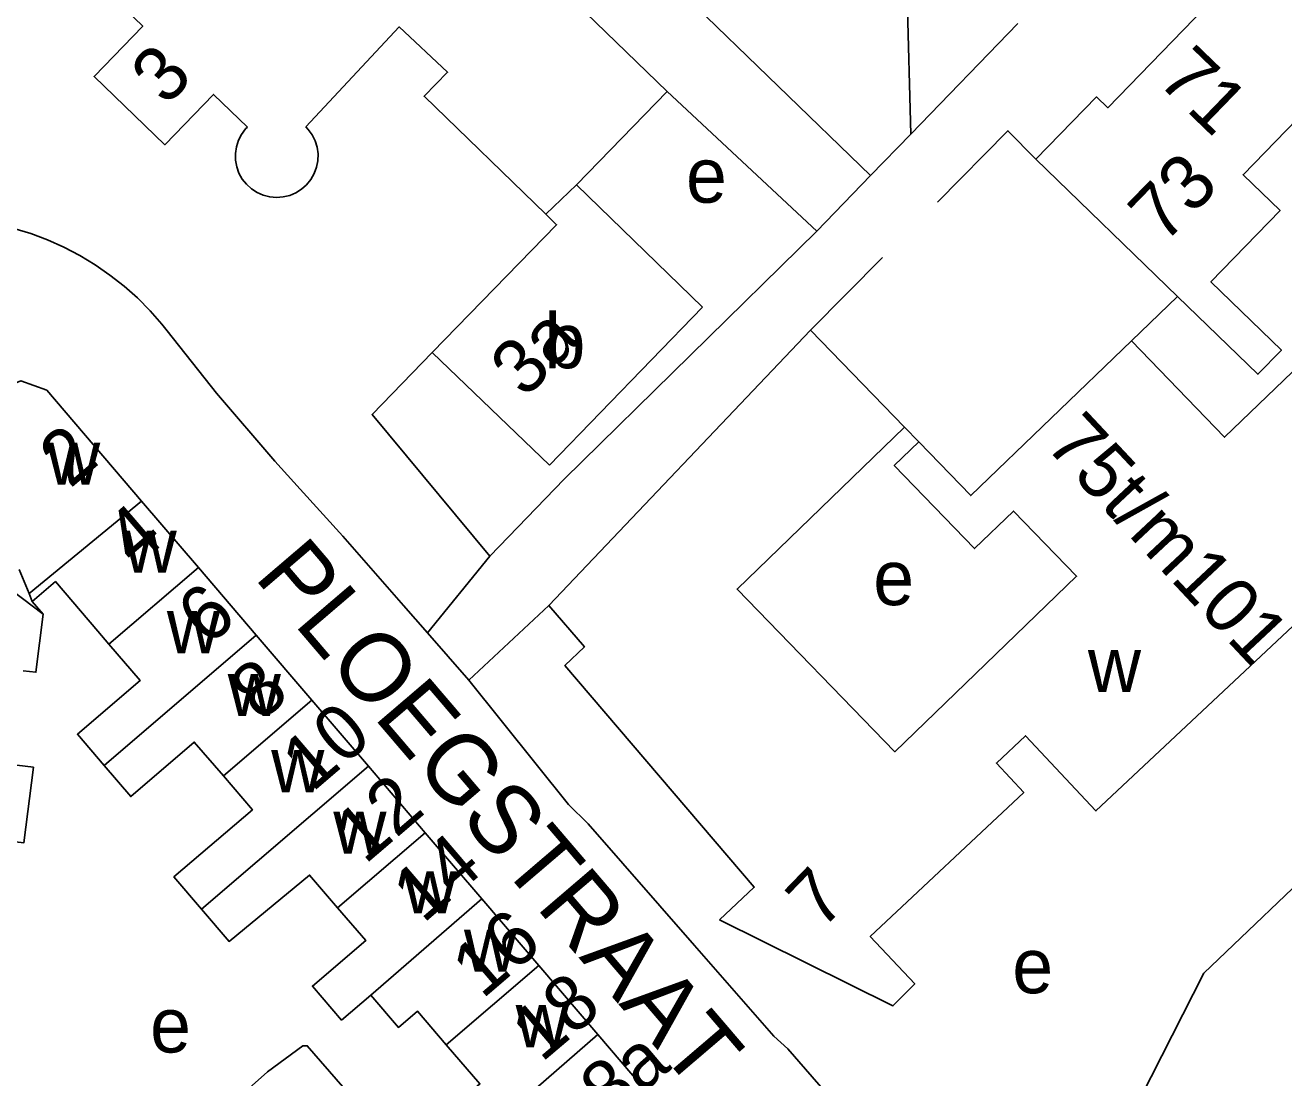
# Model space of a CAD drawing. Extents: x 159700 to 161346, y 381730 to 382922.
# Drawn here: x 160928.7 to 161020.3, y 382568 to 382644.7 of the extents above; entities that cross this region are included whole.
import ezdxf

# ---------------------------------------------------------------- set-up
doc = ezdxf.new("R2010")
doc.units = 0
for name, color, linetype in [('BLT_Basislijn', 7, 'Continuous'), ('BLT_Bebouwing', 7, 'Continuous'), ('BLT_Centroide', 7, 'Continuous'), ('BLT_Huisnummer', 7, 'Continuous'), ('BLT_Huisnummer_ tussenligend', 7, 'Continuous'), ('BLT_Huisnummer_reeks', 7, 'Continuous'), ('BLT_Onderverdeling_panden', 7, 'Continuous'), ('BLT_Straatnaam', 7, 'Continuous')]:
    doc.layers.add(name, color=color, linetype=linetype)

msp = doc.modelspace()

# ---------------------------------------------------------------- linework, layer by layer
at = {"layer": 'BLT_Basislijn'}
for p, q in [((160992.536, 382661.416), (160993.172, 382636.756)), ((160971.424, 382651.965), (160990.251, 382633.737)), ((161000.968, 382644.81), (160993.172, 382636.756)), ((160986.331, 382629.688), (160975.442, 382639.846)), ((160993.172, 382636.756), (160990.251, 382633.737)), ((160990.251, 382633.737), (160986.331, 382629.688)), ((160986.331, 382629.688), (160967.947, 382611.618)), ((161009.246, 382621.705), (161012.594, 382624.929)), ((160992.712, 382615.422), (160993.751, 382614.343)), ((160962.528, 382606.018), (160958.007, 382600.423)), ((160958.007, 382600.423), (160956.255, 382602.421)), ((160966.843, 382602.422), (160961.015, 382596.992)), ((160961.015, 382596.992), (160958.007, 382600.423)), ((160983.203, 382571.055), (160977.431, 382577.657))]:
    msp.add_line(p, q, dxfattribs=at)
for points in [[(161002.288, 382634.926), (161000.244, 382636.999), (160995.112, 382631.805)], [(160922.73, 382630.641), (160924.033, 382630.572), (160925.329, 382630.423), (160926.614, 382630.195), (160927.883, 382629.889), (160929.13, 382629.506), (160930.351, 382629.047), (160931.542, 382628.514), (160932.699, 382627.909), (160933.815, 382627.235), (160934.889, 382626.493), (160935.915, 382625.687), (160936.89, 382624.819), (160937.809, 382623.894), (160938.671, 382622.913), (160939.059, 382622.429)], [(160991.125, 382627.77), (160985.885, 382622.467)], [(160939.059, 382622.429), (160942.645, 382617.883), (160946.886, 382612.94), (160948.73, 382610.899)], [(160962.528, 382606.018), (160953.966, 382616.324), (160958.351, 382620.839)], [(160967.947, 382611.618), (160962.528, 382606.018)], [(160956.255, 382602.421), (160951.829, 382607.468), (160948.73, 382610.899)], [(161009.156, 382565.085), (161014.494, 382575.654), (161032.793, 382593.117), (161036.116, 382596.65), (161036.594, 382596.65), (161044.044, 382603.717), (161044.424, 382604.077)], [(160977.431, 382577.657), (160969.682, 382586.522), (160968.253, 382587.944), (160961.015, 382596.992)], [(160983.203, 382571.055), (160984.236, 382570.149), (160990.353, 382563.102), (161004.175, 382555.155)], [(160951.834, 382567.369), (160949.251, 382570.367), (160948.919, 382570.367), (160946.349, 382568.466), (160933.21, 382556.75), (160926.241, 382563.588)]]:
    msp.add_lwpolyline(points, dxfattribs=at)
at = {"layer": 'BLT_Bebouwing'}
for p, q in [((160975.442, 382639.846), (160968.845, 382633.054)), ((160966.843, 382602.422), (160985.885, 382622.467)), ((160958.351, 382620.839), (160966.877, 382612.646)), ((160937.194, 382610.025), (160941.331, 382605.186)), ((160941.331, 382605.186), (160945.536, 382600.266)), ((160945.536, 382600.266), (160949.584, 382595.53)), ((160949.584, 382595.53), (160953.7, 382590.715)), ((160953.7, 382590.715), (160957.84, 382585.872)), ((160957.84, 382585.872), (160961.943, 382581.072)), ((160961.943, 382581.072), (160966.103, 382576.206)), ((160966.103, 382576.206), (160970.39, 382571.189)), ((160970.39, 382571.189), (160974.509, 382566.371))]:
    msp.add_line(p, q, dxfattribs=at)
for points in [[(161002.288, 382634.926), (161006.69, 382639.464), (161007.512, 382638.667), (161043.652, 382675.94), (161042.716, 382676.847), (161047.13, 382681.401), (161051.757, 382676.918), (161050.91, 382676.044), (161056.039, 382671.074), (161056.896, 382671.959), (161063.319, 382665.739)], [(161063.319, 382665.739), (161061.58, 382663.943), (161056.461, 382668.9), (161051.433, 382663.707), (161048.821, 382666.24), (161017.358, 382633.796), (161020.05, 382631.185), (161015.023, 382626.002), (161020.151, 382621.028), (161018.437, 382619.261), (161012.594, 382624.929)], [(160944.888, 382637.259), (160942.417, 382639.648), (160938.871, 382635.981), (160933.731, 382640.951), (160937.277, 382644.618), (160934.783, 382647.031), (160934.554, 382646.794), (160932.19, 382649.082), (160934.489, 382651.461), (160934.721, 382651.239), (160938.252, 382654.894), (160937.54, 382655.583), (160940.835, 382658.993), (160937.272, 382662.286), (160936.813, 382661.811), (160935.789, 382662.8)], [(160971.424, 382651.965), (160967.233, 382656.017), (160964.973, 382653.68), (160965.757, 382652.919), (160962.607, 382649.675), (160965.221, 382647.137), (160966.538, 382648.493), (160975.442, 382639.846)], [(160966.603, 382630.92), (160957.757, 382639.509), (160959.46, 382641.263), (160955.939, 382644.564), (160949.136, 382637.295)], [(160944.888, 382637.259), (160944.755, 382637.13), (160944.463, 382636.736), (160944.24, 382636.3), (160944.09, 382635.833), (160944.018, 382635.348), (160944.025, 382634.857), (160944.112, 382634.374), (160944.277, 382633.912), (160944.514, 382633.483), (160944.817, 382633.098), (160945.18, 382632.767), (160945.591, 382632.499), (160946.04, 382632.302), (160946.515, 382632.18), (160947.003, 382632.137), (160947.492, 382632.174), (160947.969, 382632.289), (160948.42, 382632.481), (160948.835, 382632.743), (160949.201, 382633.069), (160949.51, 382633.45), (160949.753, 382633.876), (160949.923, 382634.336), (160950.017, 382634.818), (160950.031, 382635.308), (160949.965, 382635.794), (160949.821, 382636.263), (160949.603, 382636.702), (160949.317, 382637.1), (160949.136, 382637.295)], [(161012.594, 382624.929), (161002.288, 382634.926)], [(160968.845, 382633.054), (160978.013, 382624.155)], [(160958.351, 382620.839), (160967.395, 382630.151), (160966.603, 382630.92)], [(160978.013, 382624.155), (160966.877, 382612.646)], [(160985.885, 382622.467), (160992.712, 382615.422)], [(160993.751, 382614.343), (160997.537, 382610.427), (161009.246, 382621.705)], [(161009.246, 382621.705), (161016.01, 382614.682), (161022.801, 382621.223), (161028.449, 382615.252), (161031.308, 382617.935)], [(160923.444, 382616.762), (160928.393, 382618.774), (160930.286, 382618.107), (160937.194, 382610.025)], [(160992.712, 382615.422), (160980.533, 382603.619), (160992.015, 382591.77), (161005.239, 382604.558), (161000.653, 382609.304), (160997.82, 382606.565), (160991.968, 382612.62), (160993.751, 382614.343)], [(161036.025, 382612.748), (161034.616, 382611.426), (161038.981, 382606.773), (161033.683, 382601.802), (161031.115, 382604.539), (161028.559, 382602.141), (161025.627, 382605.267), (161006.656, 382587.469), (161001.529, 382592.934), (160999.408, 382590.944), (161001.403, 382588.818), (160990.223, 382578.329), (160993.459, 382574.88), (160991.875, 382573.264), (160979.253, 382579.538)], [(160929.237, 382602.728), (160930.914, 382604.164), (160933.998, 382600.561)], [(160930.029, 382601.803), (160929.237, 382602.728)], [(160928.581, 382597.679), (160929.501, 382597.57), (160930.029, 382601.803)], [(160979.253, 382579.538), (160981.782, 382581.91), (160968.001, 382598.047), (160969.422, 382599.424), (160966.843, 382602.422)], [(160933.998, 382600.561), (160934.811, 382599.611)], [(160934.811, 382599.611), (160937.083, 382596.959), (160932.513, 382593.047), (160934.454, 382590.779)], [(160934.454, 382590.779), (160936.395, 382588.512), (160941.028, 382592.479), (160943.14, 382590.012)], [(160923.04, 382584.86), (160923.156, 382585.803), (160928.615, 382585.137), (160929.313, 382590.643), (160923.828, 382591.312)], [(160943.14, 382590.012), (160945.252, 382587.546), (160939.545, 382582.66), (160941.554, 382580.314)], [(160941.554, 382580.314), (160943.563, 382577.968), (160949.42, 382582.794), (160951.46, 382580.411)], [(160951.46, 382580.411), (160953.5, 382578.028), (160949.625, 382574.71), (160951.743, 382572.236), (160953.87, 382574.057)], [(160953.87, 382574.057), (160955.884, 382571.704), (160957.268, 382572.889), (160959.362, 382570.443)], [(160959.362, 382570.443), (160961.812, 382567.582), (160960.543, 382566.496), (160961.282, 382565.624), (160959.762, 382564.335), (160960.763, 382563.153), (160962.284, 382564.442), (160962.435, 382564.264)]]:
    msp.add_lwpolyline(points, dxfattribs=at)
at = {"layer": 'BLT_Onderverdeling_panden'}
for p, q in [((160968.845, 382633.054), (160966.603, 382630.92)), ((160929.002, 382603.296), (160937.194, 382610.025)), ((160928.281, 382605.044), (160929.002, 382603.296)), ((160934.811, 382599.611), (160941.331, 382605.186)), ((160929.002, 382603.296), (160929.237, 382602.728)), ((160934.454, 382590.779), (160945.536, 382600.266)), ((160943.14, 382590.012), (160949.584, 382595.53)), ((160941.554, 382580.314), (160953.7, 382590.715)), ((160951.46, 382580.411), (160957.84, 382585.872)), ((160953.87, 382574.057), (160961.943, 382581.072)), ((160959.362, 382570.443), (160966.103, 382576.206)), ((160962.435, 382564.264), (160970.39, 382571.189))]:
    msp.add_line(p, q, dxfattribs=at)
msp.add_lwpolyline([(160930.029, 382601.803), (160925.494, 382605.208), (160916.587, 382606.293)], dxfattribs=at)

# ---------------------------------------------------------------- texts
at = {"layer": 'BLT_Centroide'}
for s, p in [('e', (160976.817, 382631.758)), ('b', (160966.516, 382619.703)), ('w', (160930.312, 382611.219)), ('w', (160935.883, 382604.812)), ('e', (160990.444, 382602.451)), ('w', (160939.031, 382598.953)), ('w', (161006.069, 382596.114)), ('w', (160943.461, 382594.375)), ('w', (160946.625, 382588.828)), ('w', (160951.148, 382584.344)), ('w', (160956.25, 382580)), ('w', (160960.656, 382575.75)), ('e', (161000.565, 382574.188)), ('e', (160937.81, 382569.874)), ('w', (160964.422, 382570.25))]:
    msp.add_text(s, height=4, dxfattribs=at).set_placement(p)
at = {"layer": 'BLT_Huisnummer'}
for s, rotation, p in [('3', 46.89668, (160939.015, 382638.719)), ('3a', 45.94733, (160965.119, 382617.439)), ('2', 40.62116, (160931.973, 382610.894)), ('6', 40.56594, (160942.019, 382599.395)), ('10', 40.57448, (160949.6, 382588.767)), ('14', 40.57326, (160957.672, 382579.211)), ('18', 40.28322, (160966.294, 382569.091))]:
    msp.add_text(s, height=4, rotation=rotation, dxfattribs=at).set_placement(p)
at = {"layer": 'BLT_Huisnummer_ tussenligend'}
for s, rotation, p in [('4', 40.62116, (160936.747, 382605.141)), ('8', 40.56594, (160945.852, 382593.895)), ('12', 40.57448, (160953.44, 382583.511)), ('16', 40.57326, (160961.98, 382573.707)), ('18a', 40.20472, (160969.031, 382562.981))]:
    msp.add_text(s, height=4, rotation=rotation, dxfattribs=at).set_placement(p)
at = {"layer": 'BLT_Huisnummer_reeks'}
for s, rotation, p in [('71', 316.01093, (161010.999, 382640.584)), ('73', 45.87536, (161011.586, 382628.672)), ('75t/m101', 313.1658, (161002.849, 382614.077)), ('7', 46.00155, (160986.672, 382578.713))]:
    msp.add_text(s, height=4, rotation=rotation, dxfattribs=at).set_placement(p)
at = {"layer": 'BLT_Straatnaam'}
msp.add_text('PLOEGSTRAAT', height=5, rotation=310.52323, dxfattribs=at).set_placement((160945.314, 382604.479))

doc.saveas('drawing.dxf')
